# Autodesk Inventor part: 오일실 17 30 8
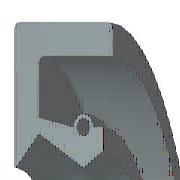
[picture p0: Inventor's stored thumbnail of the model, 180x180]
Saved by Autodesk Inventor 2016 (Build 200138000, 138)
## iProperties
Created: 2012-02
Part Number: 오일실 17 30 8
Material: 고무
Description: 오일-실
Document SubType Name: Modeling
Standard: KS B 2804
Designer: mduedu
Standards Organization: KS
Language: ko-KR
Size Designation: D - 17 30 8
Categories: <MemberInstance><Categories><Category DisplayName="샤프트 부품" InternalName="7f7aeb1f-a693-4053-b835-cee3144e0d98" Mnemonic="SHFT"><Category DisplayName="실링" Intern
Density: 0.93 g/cm^3
Appearance: 고무 - 검은색 - 버전 1.1
Mass: 2.05797 g
Surface Area: 29.3036 cm^2
Volume: 2.21288 cm^3
IsCustomPart: 1
Author: mduedu
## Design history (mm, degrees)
revolve "본체" stored, may be unused: angle "d17" = 90 deg
revolve "스프링1" stored, may be unused: angle "d18" = 90 deg
body "Solid1"
sketch "스케치1"
  geometry: L1 (0, 15)-(8, 15); L2 (8, 13.25)-(1.75, 13.25); L3 (1.75, 10.25)-(4.9, 8.5); L4 (4.9, 8.5)-(0, 8.5); L5 (0, 0)-(9.586, 0) reference; L6 (4.9, 8.5)-(6.3, 9.375); L7 (0, 18)-(0, -3) reference; L8 (-1.941, 0)-(11.507, 0) reference; L9 (4.2, 10.6)-(1.75, 11.21); L10 (1.75, 11.21)-(1.75, 13.25); L11 (0, 15)-(0, 8.588); L12 (4.9, 8.5)-(0, 8.5); L13 (1.75, 10.25)-(0.152, 8.528); L14 (8, 15)-(8, 13.25); L15 (5.6, 10.6)-(6.3, 10.6); L16 (6.3, 10.6)-(6.3, 9.375); C1 r 0.455 at (4.9, 10.6); A1 r 0.7 centre (4.9, 10.6) between (5.6, 10.6) and (4.2, 10.6); A2 r 0.088 centre (0.088, 8.588) between (0, 8.588) and (0.152, 8.528); 1 further point
  constraints: 28 end point, 5 horizontal alignment, 5 point on line, 4 point on circle, 4 vertical alignment, 3 centre point, 3 tangent, 2 collinear, 2 horizontal, 2 perpendicular, 1 coincident, 1 parallel
  dimensions: "d0" = 30 diameter of L1 L5 (= SD2); "d1" = 1.75 distance of L1.end L2.start (= SD); "d2" = 0.91 diameter of C1 (= SPDI); "d3" = 1.4 diameter of A1 (= SPDA); "d4" = 17 diameter of L3.end L5 (= NND); "d5" = 20.5 diameter of L3.start L5 (= TKDM); "d7" = 22.42 diameter of L9.end L5 (= TKDM + 0.24 x SWDT); "d8" = 1.75 distance between parallel lines of L11 L10 (= SD); "d9" = 4.9 distance from line of L11 C1.centre (= SPDST); "d10" = 21.2 diameter of C1.centre L5 (= HLDM); "d11" = 0.0875 radius of A2 (= 0.25 x LAB); "d12" = 6.3 distance between parallel lines of L11 L16 (= SDI); "d13" = 18.75 diameter of L6.end L5 (= ABDM); "d14" = 8 distance from line of L11 L1.end (= SWDT)
fillet "모깎기1" dims "d6" = 0.3 (= RR)
other parameters: "SD2" = 30 [user parameter; used in 1 equation term], "SWDT" = 8 [user parameter; used in 2 equation terms], "RR" = 0.3 [user parameter; used in 1 equation term], "SD" = 1.75 [user parameter; used in 2 equation terms], "NND" = 17 [user parameter; used in 1 equation term], "SPDA" = 1.4 [user parameter; used in 1 equation term], "SPDI" = 0.91 [user parameter; used in 1 equation term], "TKDM" = 20.5 [user parameter; used in 2 equation terms], "HLDM" = 21.2 [user parameter; used in 1 equation term], "ABDM" = 18.75 [user parameter; used in 1 equation term], "SDI" = 6.3 [user parameter; used in 1 equation term], "SPDST" = 4.9 [user parameter; used in 1 equation term], "LAB" = 0.35 [user parameter; used in 1 equation term], "d15" = 0, "d16" = 0, "d19" = 0
